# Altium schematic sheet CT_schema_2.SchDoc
size 312 x 238 mm
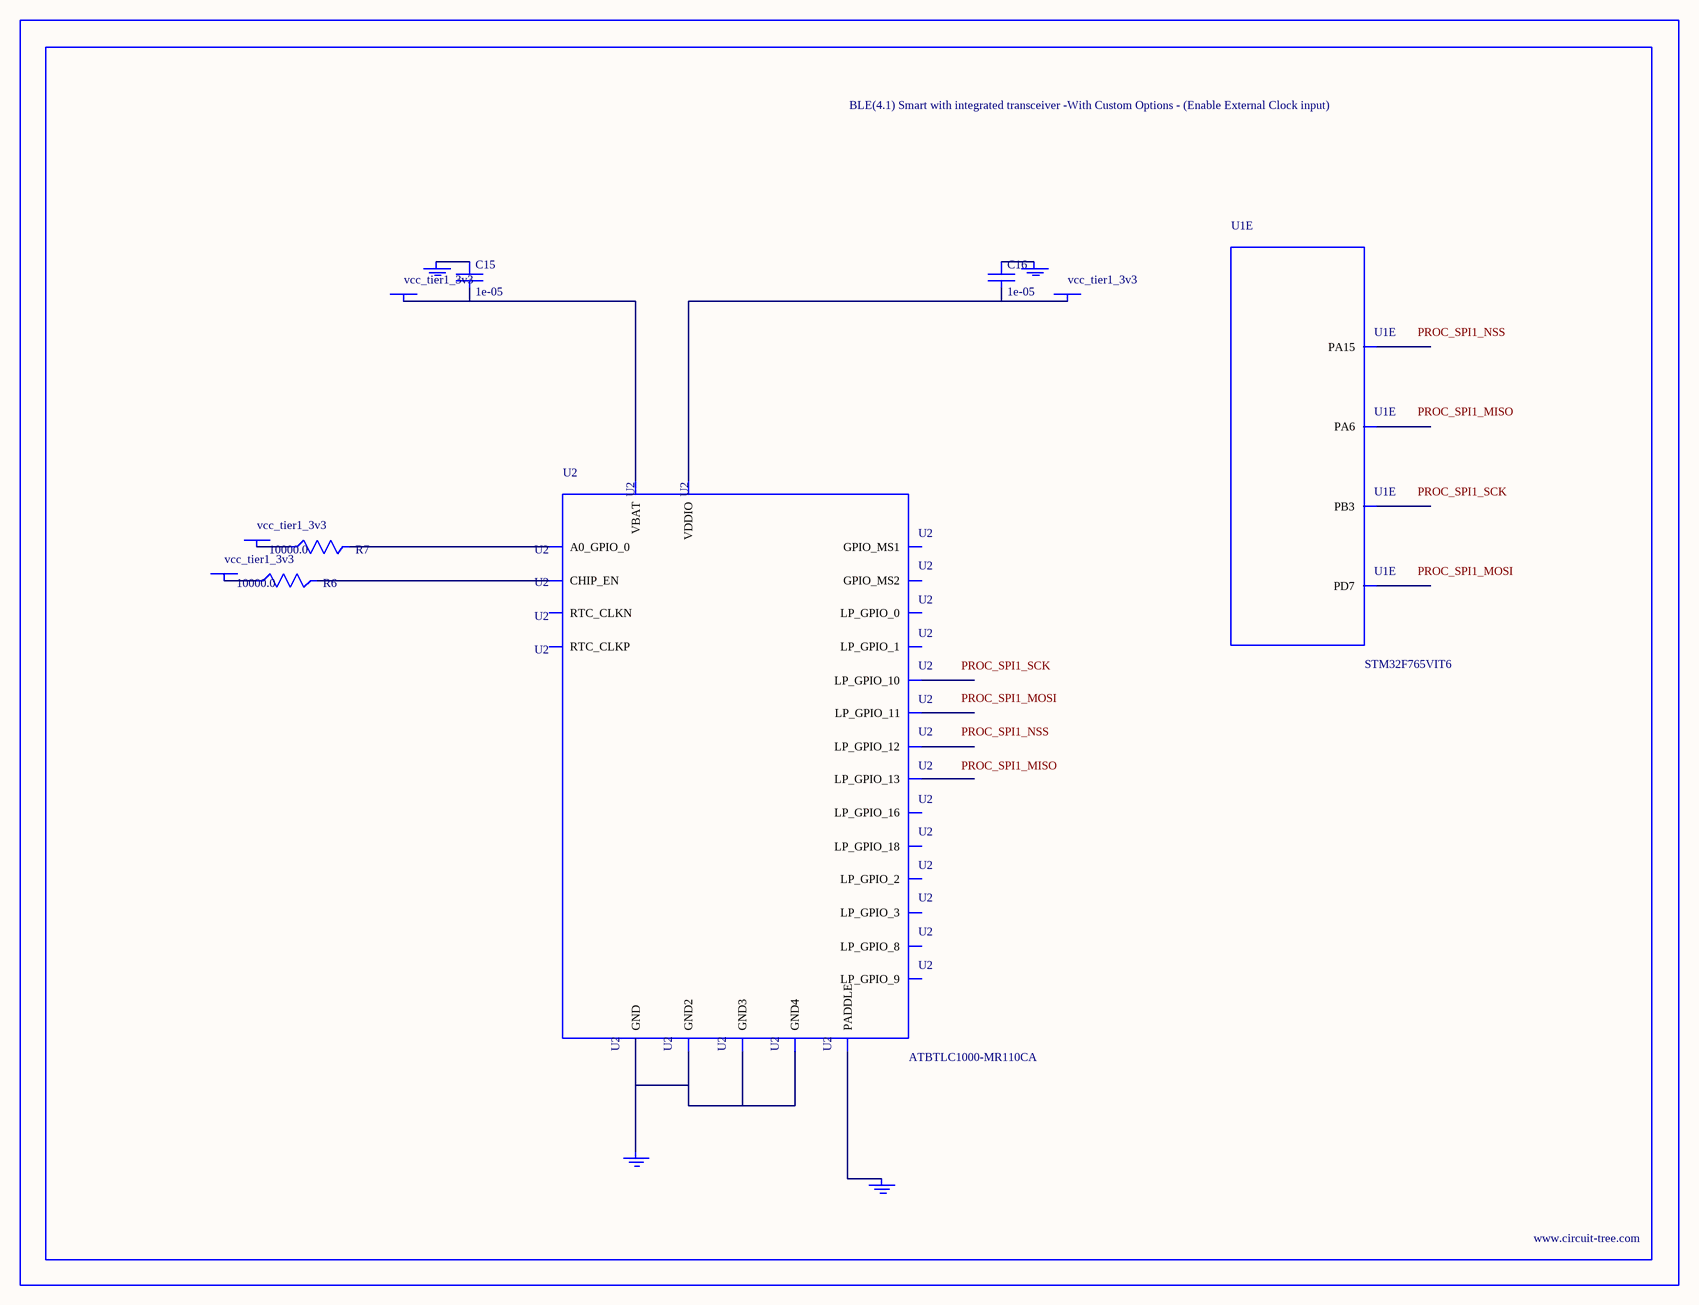
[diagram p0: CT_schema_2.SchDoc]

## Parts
BORDER1  (no value)
C15  1e-05  [C0805]
C16  1e-05  [C0805]
GND_INSTANCE_1_0  (no value)
GND_INSTANCE_1_1  (no value)
GND_INSTANCE_1_2  (no value)
GND_INSTANCE_1_3  (no value)
POWER_INSTANCE_1_0  vcc_tier1_3v3
POWER_INSTANCE_1_1  vcc_tier1_3v3
POWER_INSTANCE_1_2  vcc_tier1_3v3
POWER_INSTANCE_1_3  vcc_tier1_3v3
R6  10000.0  [R0603]
R7  10000.0  [R0603]
U1  STM32F765VIT6  [LQFP100]  (part E of 10)
U2  ATBTLC1000-MR110CA  [ATBTLC1000-MR110CA]

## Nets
NetC15_1: C15.1 GND_INSTANCE_1_0.0(GND)
NetC15_2: C15.2 POWER_INSTANCE_1_0.0(PWR) U2.6(VBAT)
NetC16_1: C16.1 GND_INSTANCE_1_1.0(GND)
NetC16_2: C16.2 POWER_INSTANCE_1_3.0(PWR) U2.22(VDDIO)
NetGND_INSTANCE_1_2_0: GND_INSTANCE_1_2.0(GND) U2.25(PADDLE)
NetGND_INSTANCE_1_3_0: GND_INSTANCE_1_3.0(GND) U2.1(GND) U2.9(GND2) U2.13(GND3) U2.24(GND4)
NetPOWER_INSTANCE_1_1_0: POWER_INSTANCE_1_1.0(PWR) R6.1
NetPOWER_INSTANCE_1_2_0: POWER_INSTANCE_1_2.0(PWR) R7.1
NetR6_2: R6.2 U2.17(CHIP_EN)
NetR7_2: R7.2 U2.20(A0_GPIO_0)

Not connected (* = marked no-connect by the designer): U1 30(PA6) 77(PA15) 88(PD7) 89(PB3); U2 2(LP_GPIO_0) 3(LP_GPIO_1) 4(LP_GPIO_2) 5(LP_GPIO_3) 7(LP_GPIO_8) 8(LP_GPIO_9) 10(LP_GPIO_10) 11(LP_GPIO_11) 12(LP_GPIO_12) 14(LP_GPIO_13) 15(GPIO_MS1) 16(GPIO_MS2) 18(RTC_CLKP) 19(RTC_CLKN) 21(LP_GPIO_16) 23(LP_GPIO_18)

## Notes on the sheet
- Labels drawn without touching a wire or pin: PROC_SPI1_MISO, PROC_SPI1_MOSI, PROC_SPI1_NSS, PROC_SPI1_SCK

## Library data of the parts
BORDER1 = BORDER_PAGE1
C15 C16 = C0805C106K8RACTU
GND_INSTANCE_1_0-GND_INSTANCE_1_3 = GND
POWER_INSTANCE_1_0-POWER_INSTANCE_1_3 = PWR
R6 R7 = RC0603JR-0710KL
